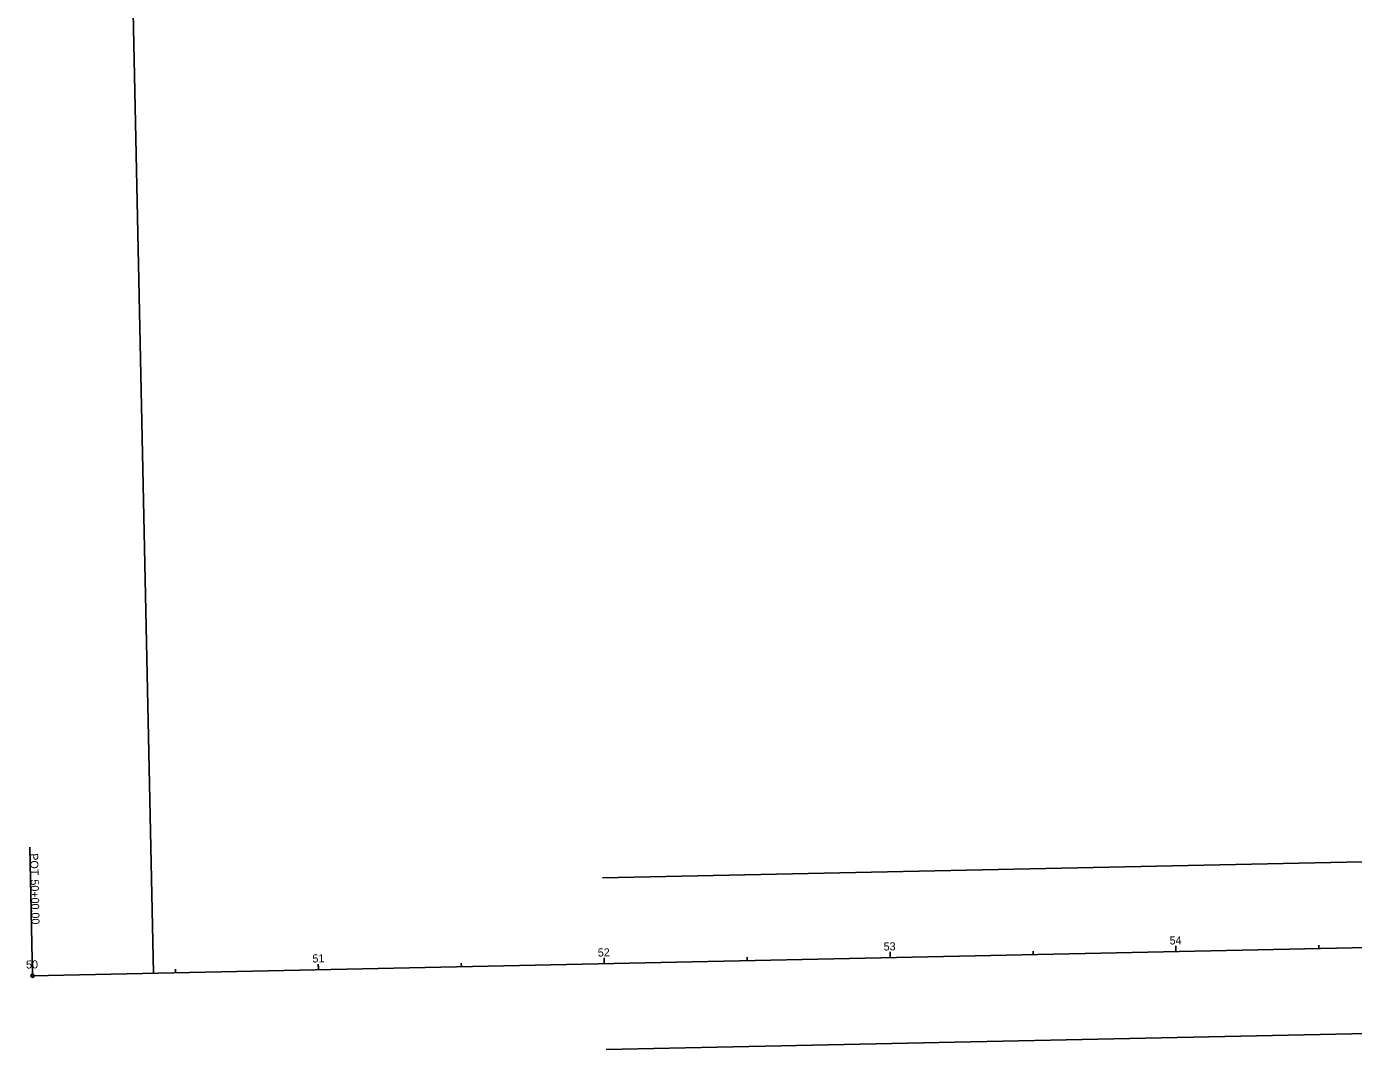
# Model space of a CAD drawing. Extents: x 2402033 to 2407434, y 498266 to 500417.
# Drawn here: x 2402032.6 to 2402496.7, y 498619.6 to 498977.4 of the extents above; entities that cross this region are included whole.
import ezdxf

# ---------------------------------------------------------------- set-up
doc = ezdxf.new("R2010")
doc.units = 0
for name, color, linetype in [('DR_P_Ditch', 7, 'Continuous'), ('GK_Drainage_Nodes', 7, 'Continuous'), ('PV_P_EOP', 7, 'Continuous'), ('PV_P_Shoulder', 7, 'Continuous'), ('RD_P_GR_Lt', 7, 'Continuous'), ('RD_P_GR_Rt', 7, 'Continuous'), ('SN_X_Public', 7, 'Continuous'), ('UT_X_Cable_TV_FO', 7, 'Continuous'), ('UT_X_Electric_Cells', 7, 'Continuous')]:
    doc.layers.add(name, color=color, linetype=linetype)

msp = doc.modelspace()

# ---------------------------------------------------------------- linework, layer by layer
at = {"layer": 'DR_P_Ditch'}
msp.add_line((2402034.69, 498645.41), (2402033.74, 498690.4), dxfattribs=at)
msp.add_circle((2402034.69, 498645.41), 0.6, dxfattribs=at)
at = {"layer": 'GK_Drainage_Nodes'}
msp.add_line((2402034.69, 498645.41), (2402033.74, 498690.4), dxfattribs=at)
msp.add_circle((2402034.69, 498645.41), 0.6, dxfattribs=at)
at = {"layer": 'PV_P_EOP'}
msp.add_line((2402034.69, 498645.41), (2403004.47, 498665.82), dxfattribs=at)
at = {"layer": 'PV_P_Shoulder'}
for p, q in [((2402334.62, 498651.72), (2402334.6, 498652.92)), ((2402434.6, 498653.83), (2402434.57, 498655.02)), ((2402034.69, 498645.41), (2402034.65, 498647.41)), ((2402134.67, 498647.51), (2402134.64, 498648.71)), ((2402234.64, 498649.62), (2402234.62, 498650.82))]:
    msp.add_line(p, q, dxfattribs=at)
at = {"layer": 'RD_P_GR_Lt'}
for p, q in [((2402334.62, 498651.72), (2402334.58, 498653.72)), ((2402384.61, 498652.77), (2402384.59, 498653.97)), ((2402434.6, 498653.83), (2402434.56, 498655.82)), ((2402484.59, 498654.88), (2402484.56, 498656.08)), ((2402034.69, 498645.41), (2402034.65, 498647.41)), ((2402084.68, 498646.46), (2402084.65, 498647.66)), ((2402134.67, 498647.51), (2402134.62, 498649.51)), ((2402184.65, 498648.56), (2402184.63, 498649.76)), ((2402234.64, 498649.62), (2402234.6, 498651.62)), ((2402284.63, 498650.67), (2402284.61, 498651.87))]:
    msp.add_line(p, q, dxfattribs=at)
at = {"layer": 'RD_P_GR_Rt'}
msp.add_line((2402034.69, 498645.41), (2402033.74, 498690.4), dxfattribs=at)
msp.add_circle((2402034.69, 498645.41), 0.6, dxfattribs=at)
at = {"layer": 'SN_X_Public'}
msp.add_line((2402034.69, 498645.41), (2402034.65, 498647.41), dxfattribs=at)
at = {"layer": 'UT_X_Cable_TV_FO'}
msp.add_line((2402051.17, 499873.2), (2402076.99, 498646.3), dxfattribs=at)
at = {"layer": 'UT_X_Electric_Cells'}
msp.add_line((2402235.27, 498619.62), (2402959.93, 498634.88), dxfattribs=at)
msp.add_lwpolyline([(2402234.01, 498679.61), (2403003.76, 498695.81), (2403031.12, 498696.54)], dxfattribs=at)

# ---------------------------------------------------------------- texts
at = {"layer": 'DR_P_Ditch'}
for s, p in [('POT', (2402033.83, 498688.19)), ('50+00.00', (2402034.03, 498679.06))]:
    msp.add_text(s, height=2.8, rotation=271.2059, dxfattribs=at).set_placement(p)
at = {"layer": 'GK_Drainage_Nodes'}
for s, p in [('POT', (2402033.83, 498688.19)), ('50+00.00', (2402034.03, 498679.06))]:
    msp.add_text(s, height=2.8, rotation=271.2059, dxfattribs=at).set_placement(p)
at = {"layer": 'PV_P_Shoulder'}
msp.add_text('50', height=2.8, rotation=1.2059, dxfattribs=at).set_placement((2402032.44, 498647.91))
at = {"layer": 'RD_P_GR_Lt'}
for s, p in [('53', (2402332.39, 498654.22)), ('54', (2402432.4, 498656.33)), ('51', (2402132.59, 498650.02)), ('52', (2402232.4, 498652.12)), ('50', (2402032.44, 498647.91))]:
    msp.add_text(s, height=2.8, rotation=1.2059, dxfattribs=at).set_placement(p)
at = {"layer": 'RD_P_GR_Rt'}
for s, p in [('POT', (2402033.83, 498688.19)), ('50+00.00', (2402034.03, 498679.06))]:
    msp.add_text(s, height=2.8, rotation=271.2059, dxfattribs=at).set_placement(p)
at = {"layer": 'SN_X_Public'}
msp.add_text('50', height=2.8, rotation=1.2059, dxfattribs=at).set_placement((2402032.44, 498647.91))

doc.saveas('drawing.dxf')
